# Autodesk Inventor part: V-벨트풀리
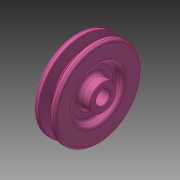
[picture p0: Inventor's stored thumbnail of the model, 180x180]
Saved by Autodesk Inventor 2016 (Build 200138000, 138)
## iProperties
Created: 2015-11
Part Number: V-벨트풀리
Material: 강철, 탄소
Document SubType Name: Modeling
Designer: mduedu
Density: 1 g/cm^3
Appearance: 분홍색
Author: mduedu
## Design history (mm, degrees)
sketch "스케치1"
  geometry: L1 (-9.5, 0)-(9.5, 0); L2 (0, 0)-(0, 37.7); L3 (-4.825, 37.7)-(-9.5, 37.7); L4 (-9.5, 37.7)-(-9.5, 0); L5 (0, 28.7)-(-2.074, 28.7); L6 (-2.074, 28.7)-(-4.825, 37.7); L7 (4.825, 37.7)-(9.5, 37.7); L8 (9.5, 37.7)-(9.5, 0); L9 (0, 28.7)-(2.074, 28.7); L10 (2.074, 28.7)-(4.825, 37.7); L11 (-9.5, 35)-(9.5, 35); 3 further points
  constraints: 22 end point, 7 point on line, 4 perpendicular, 3 symmetric about line, 1 coincident, 1 horizontal, 1 horizontal alignment, 1 midpoint, 1 vertical
  dimensions: "d0" = 19 distance of L1.start L1.end; "d2" = 75.4 diameter of L2.end L1 (derived); "d3" = 34 deg angle of L10 L6; "d4" = 6.3 distance between parallel lines of L11 L9; "d5" = 2.7 distance between parallel lines of L7 L11; "d6" = 8 distance of point (4, 35) point (-4, 35); "d7" = 70 diameter of L11 L1
revolve "회전1" sketch "스케치1" stored, may be unused: angle "d8" = 90 deg
sketch "스케치2"
  geometry: C1 r 22.5 at (0, 0); C2 r 12.5 at (0, 0); C3 r 37.7 at (0, 0) reference; 1 further point
  constraints: 2 centre point, 2 coincident
  dimensions: "d35" = 15.2 radial gap between concentric circles of C3 C1 (computed from d5); "d36" = 10 radial gap between concentric circles of C1 C2
extrude "돌출1" cut sketch "스케치2" distance "d11" = 6; taper "d12" = 0 deg
fillet "모깎기1" dims "d13" = 3
feature "면 이동1"
fillet "모깎기2" dims "d14" = 3
fillet "모깎기3" dims "d15" = 1, "d16" = 0.5, "d17" = 2
hole "구멍1" diameter "d20" = 12; stored, may be unused: countersink angle "d24" = 90 deg, drill point angle "d26" = 118 deg; dims "d21" = 6, "d22" = 4, "d23" = 2, "d25" = 8, "d37" = 10, "d38" = 10
sketch "스케치3"
  geometry: L1 (-2, 0)-(2, 0); L2 (2, 0)-(2, 7.8); L3 (2, 7.8)-(-2, 7.8); L4 (-2, 7.8)-(-2, 0); C1 r 12.5 at (0, 0) reference; 2 further points
  constraints: 8 end point, 2 coincident, 2 parallel, 1 horizontal, 1 midpoint, 1 perpendicular
  dimensions: "d27" = 4 distance of L2.end L3.end; "d29" = 7.8 distance of L3.end L1.start
extrude "돌출2" cut sketch "스케치3" stored distance "d30" = 6; taper "d31" = 0 deg
chamfer "모따기1" distance "d32" = 0.5; stored, may be unused: second distance "d33" = 2, angle "d34" = 45 deg
node "솔리드1"
mirror "대칭1"
